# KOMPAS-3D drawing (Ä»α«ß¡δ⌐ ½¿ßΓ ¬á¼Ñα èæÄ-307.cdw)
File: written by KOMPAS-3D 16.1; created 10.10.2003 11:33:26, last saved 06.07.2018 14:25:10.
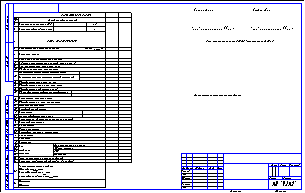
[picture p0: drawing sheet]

Sheet 1: custom format 470 x 297 mm, landscape

Title block, sheet 1: organisation: АО "ЧЭАЗ"; stored path: D:\Заказы\Уфа\Схема монтажа №1.cdw

Views: Вид 1, Вид 2, Вид 3, Вид 4, Вид 5
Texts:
  Normal
  Body Text
  heading 1
  heading 2
  heading 3
  heading 4
  heading 5
  heading 6
  heading 7
  heading 8
  heading 9
  Body Text 2
  header
  caption
  footer
  toc 1
  toc 2
  toc 3
  toc 4
  toc 5
  toc 6
  toc 7
  toc 8
  toc 9
  Body Text Indent 2
  annotation text
  Plain Text
  Courier New
  Body Text Indent 3
  Title
  Document Map
  Tahoma
  Body Text 3
  Block Text
  ArialMT
  font5
  font6
  font7
  xl24
  xl25
  xl26
  xl27
  xl28
  xl29
  xl30
  xl31
  xl32
  xl33
  xl34
  xl35
  xl36
  xl37
  xl38
  xl39
  xl40
  xl41
  xl42
  xl43
  xl44
  xl45
  xl46
  xl47
  xl48
  xl49
  xl50
  xl51
  xl52
  xl53
  xl54
  xl55
  xl56
  xl57
  xl58
  xl59
  xl60
  xl61
  xl62
  xl63
  xl64
  xl65
  xl66
  xl67
  xl68
  xl69
  xl70
  xl71
  xl72
  xl73
  xl74
  xl75
  xl76
  xl77
  xl78
  xl79
  xl80
  xl81
  xl82
  xl83
  xl84
  xl85
  xl86
  xl87
  xl88
  xl89
  xl90
  xl91
  xl92
  xl93
  xl94
  xl95
  xl96
  xl97
  xl98
  xl99
  xl100
  xl101
  xl102
  xl103
  xl104
  xl105
  xl106
  xl107
  xl108
  xl109
  xl110
  xl111
  xl112
  xl113
  xl114
  xl115
  xl116
  xl117
  xl118
  xl119
  xl120
  xl121
  xl122
  xl123
  xl124
  xl125
  xl126
  xl127
  xl128
  xl129
  xl130
  xl131
  xl132
  xl133
  xl134
  Iniiaiie oaeno
  xl22
  xl23
  Лит-Масса-Масштаб
  Материал-Предприятие
  Утверждаю
  Дополнительные технические требования:
  Согласовано
  ЗАПРАШИВАЕМЫЕ ДАННЫЕ
  № поз
  Порядковый номер шкафа
  Номинальное напряжение КСО
  СХЕМА ГЛАВНЫХ ЦЕПЕЙ
  Номинальный ток сборных шин
  Номенклатурное обозначение камеры                          КСО-307_____У3
  Назначение камеры
  Номер схемы вспомогательных цепей
  Род тока вспомогательных цепей и напряжение, В
  Комм. аппарат., тип, ток, напряжение
  Тип блока управления выключателя
  Разъединитель трехпозиционный элегазовый
  Трансформатор тока, тип, кл. т.
  Трансформатор напряжения, тип, кл.т.
  Трансформатор собственных нужд
  Тип предохранителей, ток плавкой вставки
  Ограничитель перенапряжения
  Трансформатор н.п., тип, количество
  Шинный разъединитель
  Линейный разъединитель
  Заземлитель
  Емкостной индикатор напряжения
  Количество эл. бл./замков заземляющих ножей
  Конечный выключатель
  Тип счетчиков
  Обогрев счетчиков
  Устройство защиты и автоматики
  Блок питания
  Амперметр
  Вольтметр
  Реле,
  требующие
  уточнения
  Защита от замык. на землю
  Токовая отсечка
  МТЗ
  Перегрузка
  Марка, количество и сечение кабелей
  Исполнение ввода/вывода (В-воздух, К - кабель)
  В комплект поставки входят:
  Шинный мост  -  шт.
  Правый боковой экран   шт.,
  Боковой экран сборных шин    шт.
  Заказчик:
  Объект:
  Выключатель нагрузки трехпозиционный элегазовый
  План расположения камер КСО-307 (высота камер 1600 мм)
  Основная_0
  K5LT_THIN_RGB_0_0_0_THICK_0.18
  Подпись 1
  K5LT32769_RGB_0_0_0_THICK_0.18
  Стили документа
Dimensions and other numbers on the sheet: 1; 2; 4; 3; 5; 6; 7; 8; 9; 10; 11; 12; 13; 14; 15; 16; 17; 18; 19; 20; 21; 22; 23; 24; 25; 26; 27; 28; 29; 30; 31; 32; 33; 34; 35; 36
